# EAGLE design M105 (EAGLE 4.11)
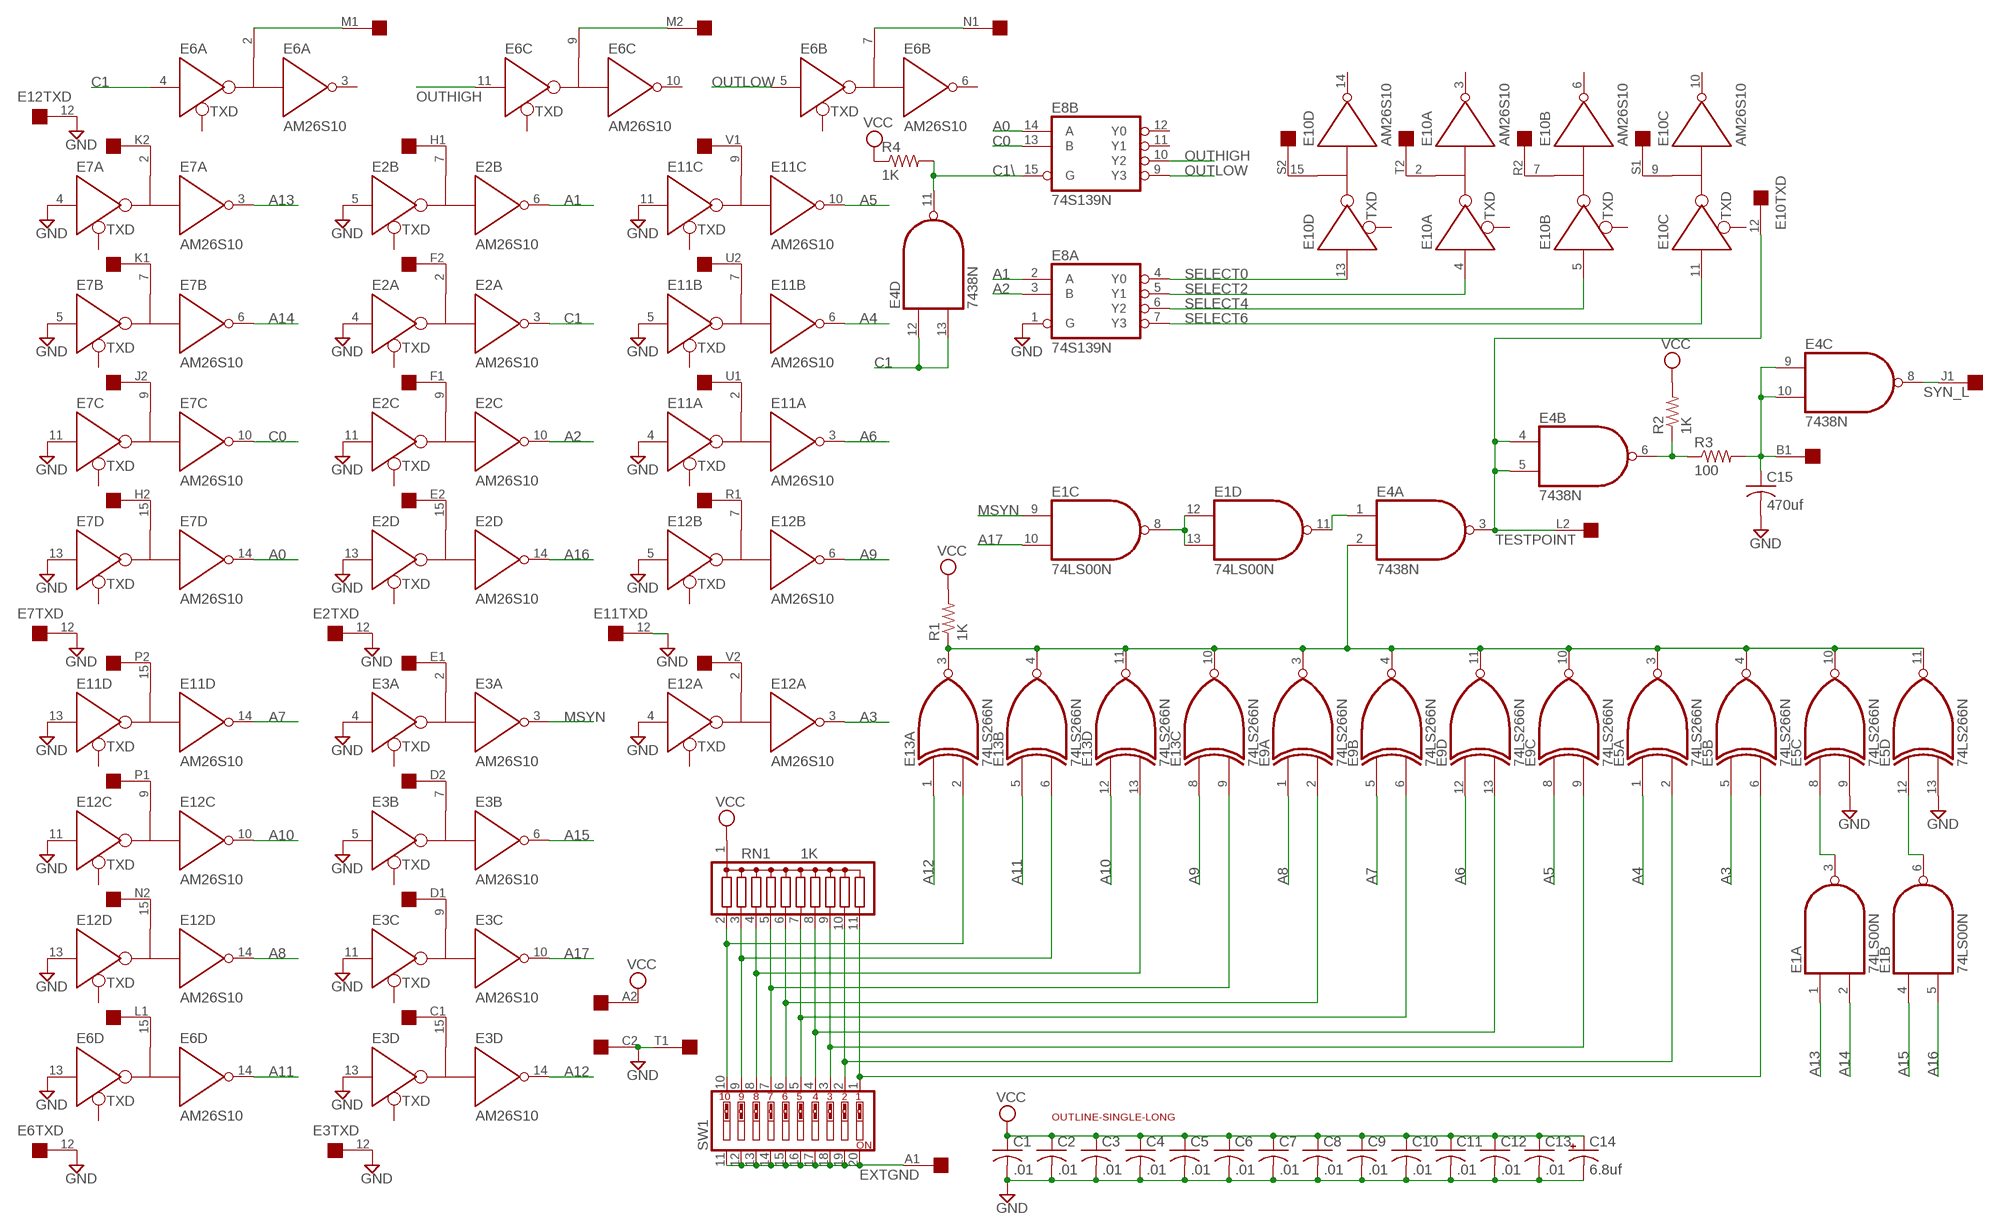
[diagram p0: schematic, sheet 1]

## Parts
C1  .01  C-US050-025X075  [C050-025X075]
C2  .01  C-US050-025X075  [C050-025X075]
C3  .01  C-US050-025X075  [C050-025X075]
C4  .01  C-US050-025X075  [C050-025X075]
C5  .01  C-US050-025X075  [C050-025X075]
C6  .01  C-US050-025X075  [C050-025X075]
C7  .01  C-US050-025X075  [C050-025X075]
C8  .01  C-US050-025X075  [C050-025X075]
C9  .01  C-US050-025X075  [C050-025X075]
C10  .01  C-US050-025X075  [C050-025X075]
C11  .01  C-US050-025X075  [C050-025X075]
C12  .01  C-US050-025X075  [C050-025X075]
C13  .01  C-US050-025X075  [C050-025X075]
C14  6.8uf  CPOL-USE15-5AXIAL  [E15-5]
C15  470uf  C-US050-025X075  [C050-025X075]
E1  74LS00N  [DIL14]
E2  AM26S10  [DIL16]
E3  AM26S10  [DIL16]
E4  7438N  [DIL14]
E5  74LS266N  [DIL14]
E6  AM26S10  [DIL16]
E7  AM26S10  [DIL16]
E8  74S139N  [DIL16]
E9  74LS266N  [DIL14]
E10  AM26S10  [DIL16]
E11  AM26S10  [DIL16]
E12  AM26S10  [DIL16]
E13  74LS266N  [DIL14]
R1  1K  R-US_0207/10  [0207/10]
R2  1K  R-US_0207/10  [0207/10]
R3  100  R-US_0207/10  [0207/10]
R4  1K  R-US_0207/10  [0207/10]
RN1  1K  G10R  [SIL11]
SW1  SW_DIP-10  [EDG-10]
U$1  SINGLE  [EDGE-CON2]
U$2  OUTLINE-SINGLE-LONG  [SINGLE-LONG]

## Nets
A0: E7.14(D:R) E8.14(B:A)
A1: E2.6(B:R) E8.2(A:A)
A2: E2.10(C:R) E8.3(A:B)
A3: E5.5(B:I0) E12.3(A:R)
A4: E5.1(A:I0) E11.6(B:R)
A5: E9.8(C:I0) E11.10(C:R)
A6: E9.12(D:I0) E11.3(A:R)
A7: E9.5(B:I0) E11.14(D:R)
A8: E9.1(A:I0) E12.14(D:R)
A9: E12.6(B:R) E13.8(C:I0)
A10: E12.10(C:R) E13.12(D:I0)
A11: E6.14(D:R) E13.5(B:I0)
A12: E3.14(D:R) E13.1(A:I0)
A13: E1.1(A:I0) E7.3(A:R)
A14: E1.2(A:I1) E7.6(B:R)
A15: E1.4(B:I0) E3.6(B:R)
A16: E1.5(B:I1) E2.14(D:R)
A17: E1.10(C:I1) E3.10(C:R)
C0: E7.10(C:R) E8.13(B:B)
C1: E2.3(A:R) E4.12(D:I0) E4.13(D:I1) E6.4(A:D)
C1\: E4.11(D:O) E8.15(B:G) R4.2
EXTGND: SW1.11 SW1.12 SW1.13 SW1.14 SW1.15 SW1.16 SW1.17 SW1.18 SW1.19 SW1.20 U$1.A1
GND: C1.2 C2.2 C3.2 C4.2 C5.2 C6.2 C7.2 C8.2 C9.2 C10.2 C11.2 C12.2 C13.2 C14.- C15.2 E2.4(A:D) E2.5(B:D) E2.11(C:D) E2.12(TXD:TXD) E2.13(D:D) E3.4(A:D) E3.5(B:D) E3.11(C:D) E3.12(TXD:TXD) E3.13(D:D) E5.9(C:I1) E5.13(D:I1) E6.12(TXD:TXD) E6.13(D:D) E7.4(A:D) E7.5(B:D) E7.11(C:D) E7.12(TXD:TXD) E7.13(D:D) E8.1(A:G) E11.4(A:D) E11.5(B:D) E11.11(C:D) E11.12(TXD:TXD) E11.13(D:D) E12.4(A:D) E12.5(B:D) E12.11(C:D) E12.12(TXD:TXD) E12.13(D:D) U$1.C2 U$1.T1
MSYN: E1.9(C:I0) E3.3(A:R)
N$1: E3.2(A:B) U$1.E1
N$2: E3.7(B:B) U$1.D2
N$3: E3.9(C:B) U$1.D1
N$4: E3.15(D:B) U$1.C1
N$5: E2.7(B:B) U$1.H1
N$6: E2.2(A:B) U$1.F2
N$7: E2.9(C:B) U$1.F1
N$8: E2.15(D:B) U$1.E2
N$9: E7.2(A:B) U$1.K2
N$10: E7.7(B:B) U$1.K1
N$11: E7.9(C:B) U$1.J2
N$12: E7.15(D:B) U$1.H2
N$13: E11.15(D:B) U$1.P2
N$14: E12.9(C:B) U$1.P1
N$15: E12.15(D:B) U$1.N2
N$16: E6.15(D:B) U$1.L1
N$17: E12.7(B:B) U$1.R1
N$18: E12.2(A:B) U$1.V2
N$19: E11.2(A:B) U$1.U1
N$20: E11.7(B:B) U$1.U2
N$21: E11.9(C:B) U$1.V1
N$22: E4.6(B:O) R2.1 R3.1
N$23: E10.15(D:B) U$1.S2
N$24: E10.2(A:B) U$1.T2
N$25: E10.7(B:B) U$1.R2
N$26: E10.9(C:B) U$1.S1
N$27: E6.2(A:B) U$1.M1
N$28: E6.9(C:B) U$1.M2
N$29: E1.3(A:O) E5.8(C:I0)
N$30: E1.6(B:O) E5.12(D:I0)
N$31: E1.8(C:O) E1.12(D:I0) E1.13(D:I1)
N$33: E5.6(B:I1) RN1.11 SW1.1
N$34: E5.2(A:I1) RN1.10 SW1.2
N$35: E9.9(C:I1) RN1.9 SW1.3
N$36: E9.13(D:I1) RN1.8 SW1.4
N$37: E9.6(B:I1) RN1.7 SW1.5
N$38: E9.2(A:I1) RN1.6 SW1.6
N$39: E13.9(C:I1) RN1.5 SW1.7
N$40: E13.13(D:I1) RN1.4 SW1.8
N$41: E13.6(B:I1) RN1.3 SW1.9
N$42: E13.2(A:I1) RN1.2 SW1.10
N$43: E4.2(A:I1) E5.3(A:O) E5.4(B:O) E5.10(C:O) E5.11(D:O) E9.3(A:O) E9.4(B:O) E9.10(C:O) E9.11(D:O) E13.3(A:O) E13.4(B:O) E13.10(C:O) E13.11(D:O) R1.1
N$44: C15.1 E4.9(C:I0) E4.10(C:I1) R3.2 U$1.B1
N$45: E6.7(B:B) U$1.N1
N$46: E1.11(D:O) E4.1(A:I0)
OUTHIGH: E6.11(C:D) E8.10(B:Y2)
OUTLOW: E6.5(B:D) E8.9(B:Y3)
SELECT0: E8.4(A:Y0) E10.13(D:D)
SELECT2: E8.5(A:Y1) E10.4(A:D)
SELECT4: E8.6(A:Y2) E10.5(B:D)
SELECT6: E8.7(A:Y3) E10.11(C:D)
SYN_L: E4.8(C:O) U$1.J1
TESTPOINT: E4.3(A:O) E4.4(B:I0) E4.5(B:I1) E10.12(TXD:TXD) U$1.L2
VCC: C1.1 C2.1 C3.1 C4.1 C5.1 C6.1 C7.1 C8.1 C9.1 C10.1 C11.1 C12.1 C13.1 C14.+ R1.2 R2.2 R4.1 RN1.1 U$1.A2
Unconnected: E6.3(A:R) E6.6(B:R) E6.10(C:R) E8.11(B:Y1) E8.12(B:Y0) E10.3(A:R) E10.6(B:R) E10.10(C:R) E10.14(D:R) U$1.B2

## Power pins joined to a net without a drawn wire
GND: E1.7(P:GND) E2.1(GND:GND) E2.8(PWR:GND) E3.1(GND:GND) E3.8(PWR:GND) E4.7(P:GND) E5.7(P:GND) E6.1(GND:GND) E6.8(PWR:GND) E7.1(GND:GND) E7.8(PWR:GND) E8.8(P:GND) E9.7(P:GND) E10.1(GND:GND) E10.8(PWR:GND) E11.1(GND:GND) E11.8(PWR:GND) E12.1(GND:GND) E12.8(PWR:GND) E13.7(P:GND)
VCC: E1.14(P:VCC) E2.16(PWR:VCC) E3.16(PWR:VCC) E4.14(P:VCC) E5.14(P:VCC) E6.16(PWR:VCC) E7.16(PWR:VCC) E8.16(P:VCC) E9.14(P:VCC) E10.16(PWR:VCC) E11.16(PWR:VCC) E12.16(PWR:VCC) E13.14(P:VCC)

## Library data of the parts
C1-C13 C15 = rcl:C-US: CAPACITOR, American symbol
C14 = rcl:CPOL-US: POLARIZED CAPACITOR, American symbol
E1 = 74xx-jameco:74*00: Quad 2-input NAND gate
E2 E3 E6 E7 E10-E12 = dec-con:AM26S10: Bus Transceiver
E4 = 74xx-jameco:74*38: Quad 2-input NAND gate, open collector output
E5 E9 E13 = 74xx-jameco:74*266: Quadruple EXCLUSIVE-NOR (XNOR), open-collector
E8 = 74xx-jameco:74*139: Dual 2-line to 4-line DECODER/DEMULTIPLEXER
R1-R4 = rcl:R-US_: RESISTOR, American symbol
RN1 = resistor-sil:G10R: SIL RESISTOR
SW1 = special:SW_DIP-10: DIP SWITCH
U$1 = dec-con:SINGLE: Single-Height DEC board
U$2 = dec-con:OUTLINE-*: Board outlines for DEC boards.

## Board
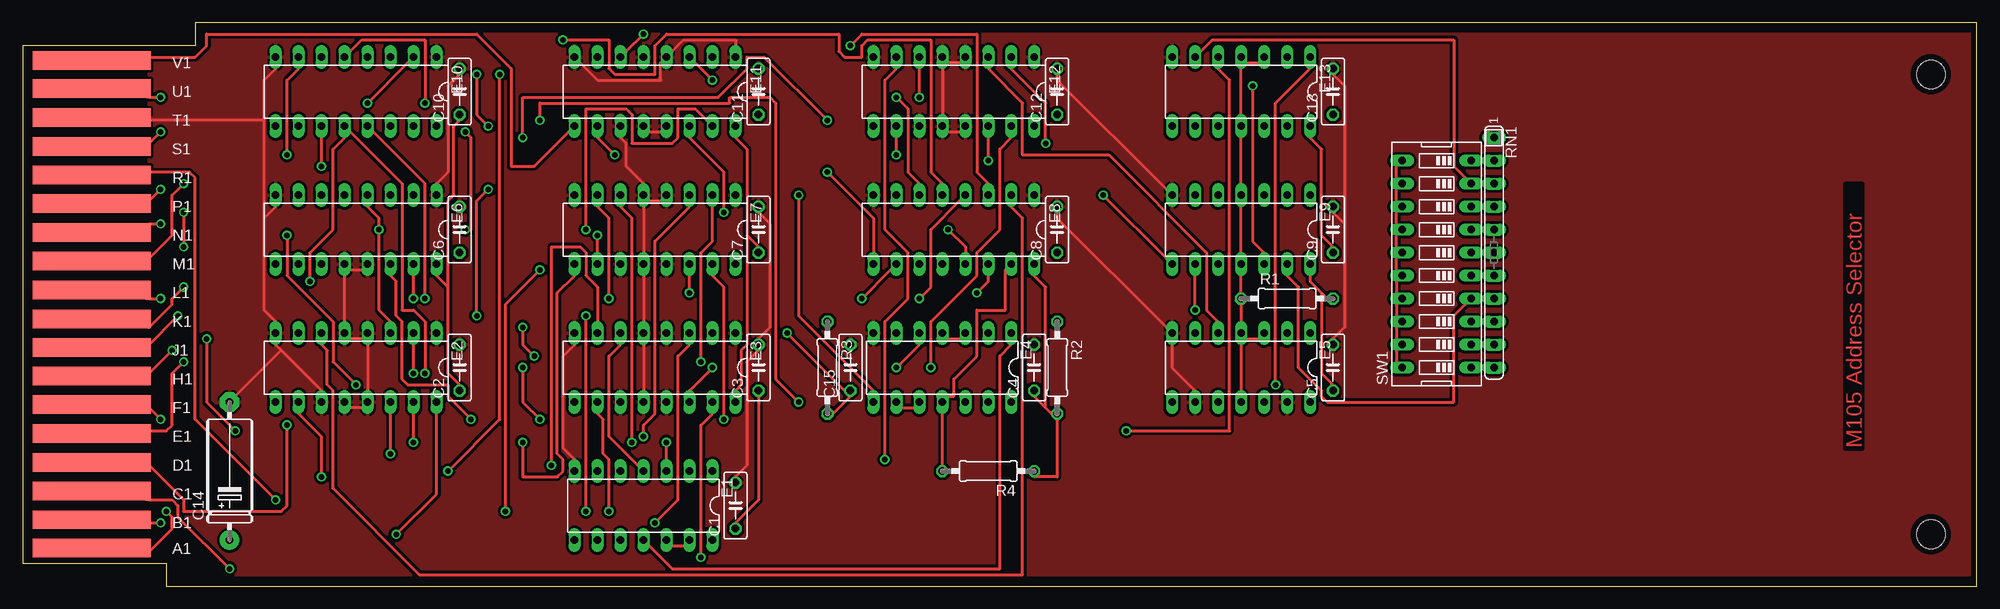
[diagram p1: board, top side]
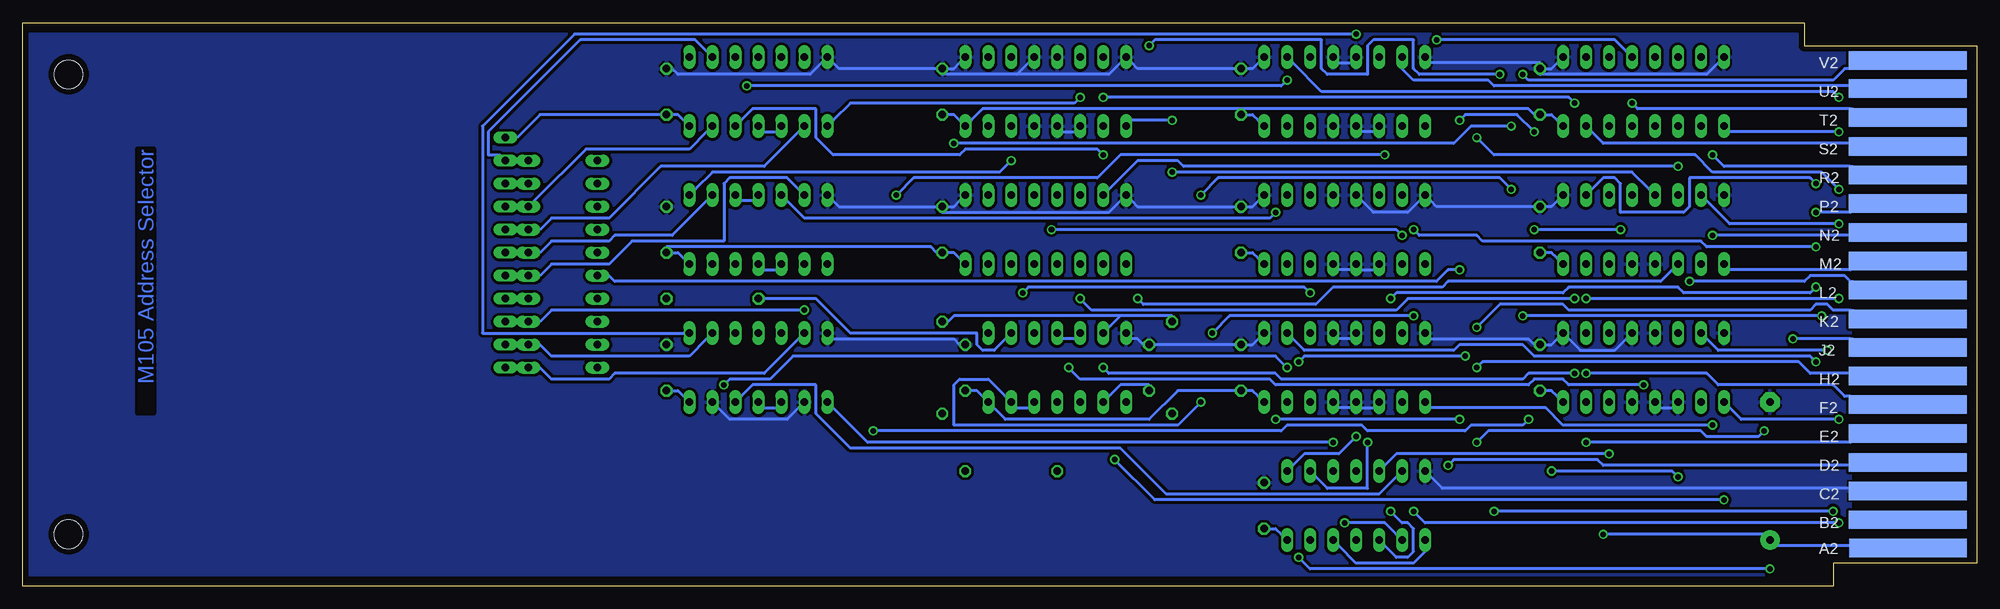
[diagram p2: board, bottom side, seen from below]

Size 215.9 x 62.23 mm. Coordinates in mm from the lower left corner, seen from the top.
Outline: 15.88,2.54 15.88,0
Copper layers (1*16): Top 0.035mm / dielectric 1.5mm / Bottom 0.035mm
Design rules "15mils": minimum track width 13mil, minimum drill 24mil, track to track 12mil, track to pad 10mil, pad to pad 10mil, via to via 10mil, smd to smd 10mil, copper to edge 25mil, drill to drill 10mil, minimum pad ring 10mil, minimum via ring 8mil, stop-mask expansion 0mil, vias tented up to drill 0mil, thermal gap 10mil

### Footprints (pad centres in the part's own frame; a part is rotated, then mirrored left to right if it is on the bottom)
C050-025X075 = drill 0.813 octagon: 1 -2.54,0; 2 2.54,0
E15-5 = drill 0.813 pad 2.159 round: + -7.62,0 | drill 0.813 pad 2.159 octagon: - 7.62,0
DIL14 = drill 0.813 long: 1 -7.62,-3.81; 2 -5.08,-3.81; 3 -2.54,-3.81; 4 0,-3.81; 5 2.54,-3.81; 6 5.08,-3.81; 7 7.62,-3.81; 8 7.62,3.81; 9 5.08,3.81; 10 2.54,3.81; 11 0,3.81; 12 -2.54,3.81; 13 -5.08,3.81; 14 -7.62,3.81
DIL16 = drill 0.813 long: 1 -8.89,-3.81; 2 -6.35,-3.81; 3 -3.81,-3.81; 4 -1.27,-3.81; 5 1.27,-3.81; 6 3.81,-3.81; 7 6.35,-3.81; 8 8.89,-3.81; 9 8.89,3.81; 10 6.35,3.81; 11 3.81,3.81; 12 1.27,3.81; 13 -1.27,3.81; 14 -3.81,3.81; 15 -6.35,3.81; 16 -8.89,3.81
0207/10 = drill 0.813 octagon: 1 -5.08,0; 2 5.08,0
SIL11 = drill 0.813 long: 1 -12.7,0; 2 -10.16,0; 3 -7.62,0; 4 -5.08,0; 5 -2.54,0; 6 0,0; 7 2.54,0; 8 5.08,0; 9 7.62,0; 10 10.16,0; 11 12.7,0
EDG-10 = drill 0.813 long: 1 -11.43,-3.81; 2 -8.89,-3.81; 3 -6.35,-3.81; 4 -3.81,-3.81; 5 -1.27,-3.81; 6 1.27,-3.81; 7 3.81,-3.81; 8 6.35,-3.81; 9 8.89,-3.81; 10 11.43,-3.81; 11 11.43,3.81; 12 8.89,3.81; 13 6.35,3.81; 14 3.81,3.81; 15 1.27,3.81; 16 -1.27,3.81; 17 -3.81,3.81; 18 -6.35,3.81; 19 -8.89,3.81; 20 -11.43,3.81
EDGE-CON2 = smd 13.017 x 2.032: A1 7.633,4.207; B1 7.639,7.327; C1 7.636,10.489; D1 7.633,13.665; E1 7.642,16.84; F1 7.642,20.041; H1 7.642,23.19; J1 7.642,26.34; K1 7.642,29.515; L1 7.642,32.69; M1 7.642,35.89; N1 7.642,39.04; P1 7.642,42.24; R1 7.642,45.39; S1 7.642,48.565; T1 7.642,51.74; U1 7.642,54.966; V1 7.642,58.026 | smd 13.017 x 2.032 bottom: A2 7.614,4.207; B2 7.642,7.328; C2 7.617,10.49; D2 7.642,13.665; E2 7.642,16.84; F2 7.617,20.041; H2 7.617,23.19; J2 7.642,26.34; K2 7.642,29.515; L2 7.642,32.69; M2 7.642,35.89; N2 7.642,39.04; P2 7.642,42.24; R2 7.642,45.39; S2 7.642,48.565; T2 7.642,51.74; U2 7.642,54.966; V2 7.642,58.026
SINGLE-LONG = hole 3.175: 210.82,56.515; 210.82,5.715

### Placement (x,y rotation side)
C1  78.74,8.89 90 top
C2  48.26,24.13 90 top
C3  81.28,24.13 90 top
C4  111.76,24.13 90 top
C5  144.78,24.13 90 top
C6  48.26,39.37 90 top
C7  81.28,39.37 90 top
C8  114.3,39.37 90 top
C9  144.78,39.37 90 top
C10  48.26,54.61 90 top
C11  81.28,54.61 90 top
C12  114.3,54.61 90 top
C13  144.78,54.61 90 top
C14  22.86,12.7 90 top
C15  91.44,24.13 90 top
E1  68.58,8.89 180 top
E2  36.83,24.13 180 top
E3  69.85,24.13 180 top
E4  101.6,24.13 180 top
E5  134.62,24.13 180 top
E6  36.83,39.37 180 top
E7  69.85,39.37 180 top
E8  102.87,39.37 180 top
E9  134.62,39.37 180 top
E10  36.83,54.61 180 top
E11  69.85,54.61 180 top
E12  102.87,54.61 180 top
E13  134.62,54.61 180 top
R1  139.7,31.75 0 top
R2  114.3,24.13 270 top
R3  88.9,24.13 270 top
R4  106.68,12.7 180 top
RN1  162.56,36.83 270 top
SW1  156.21,35.56 90 top
U$1  0,0 0 top
U$2  0,0 0 top

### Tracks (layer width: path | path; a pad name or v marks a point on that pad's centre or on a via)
A0  (via drill 0.61)
  Top 0.33: v73.66,32.38 73.66,34.29 E7.14 | v105.41,32.38 106.68,33.66 106.68,34.29 E8.14
  Bottom 0.33: v73.66,32.38 74.3,33.02 104.78,33.02 v105.41,32.38
A1
  Top 0.33: E2.6 33.02,26.67 33.66,26.04 33.66,22.23 34.29,21.59 34.29,10.79 43.82,1.27 110.49,1.27 110.49,40.64 109.22,41.91 E8.2
A2  (via drill 0.61)
  Top 0.33: v33.02,12.06 33.02,16.51 30.48,19.05 E2.10 | v46.99,12.7 52.71,18.41 v52.71,56.52 | v91.44,59.69 92.71,60.96 105.41,60.96 105.41,45.72 106.68,44.45 E8.3
  Bottom 0.33: v33.02,12.06 33.66,12.7 v46.99,12.7 | v52.71,56.52 61.6,56.52 62.23,57.15 62.23,60.33 66.68,60.33 67.31,59.69 67.31,56.52 71.76,56.52 72.39,57.15 72.39,60.33 90.81,60.33 v91.44,59.69
A3
  Top 0.33: E5.5 132.08,29.21 130.81,30.48 130.81,36.83 120.02,47.62 110.49,47.62 110.49,53.34 106.68,57.15 E12.3
A4  (via drill 0.61)
  Top 0.33: v68.58,60.96 66.68,59.05 E11.6
  Bottom 0.33: v68.58,60.96 154.94,60.96 165.1,50.8 165.1,27.94 142.88,27.94 E5.1
A5  (via drill 0.61)
  Top 0.33: v65.41,47.62 63.5,49.53 E11.10 | v119.38,43.18 126.37,36.2 E9.8
  Bottom 0.33: v65.41,47.62 94.62,47.62 97.16,45.09 117.48,45.09 v119.38,43.18
A6  (via drill 0.61)
  Top 0.33: v76.2,55.88 74.3,57.78 E11.3 | v135.89,55.24 135.89,38.1 137.16,36.83 E9.12
  Bottom 0.33: v76.2,55.88 76.84,55.24 v135.89,55.24
A7  (via drill 0.61)
  Top 0.33: v77.47,41.27 77.47,45.72 73.66,49.53 E11.14
  Bottom 0.33: v77.47,41.27 78.11,40.64 129.54,40.64 131.45,42.55 E9.5
A8  (via drill 0.61)
  Top 0.33: v106.68,46.99 106.68,49.53 E12.14
  Bottom 0.33: v106.68,46.99 107.95,45.72 139.7,45.72 141.61,43.81 E9.1
A9  (via drill 0.61)
  Top 0.33: v99.06,53.98 99.06,57.15 E12.6
  Bottom 0.33: v99.06,53.98 99.7,53.34 124.46,53.34 126.37,51.44 E13.8
A10  (via drill 0.61)
  Top 0.33: v96.52,47.62 96.52,49.53 E12.10
  Bottom 0.33: v96.52,47.62 97.16,48.26 111.76,48.26 112.4,47.62 126.37,47.62 128.27,49.53 128.27,52.7 135.26,52.7 136.53,51.44 E13.12
A11  (via drill 0.61)
  Top 0.33: v49.53,18.41 46.99,20.95 46.99,22.23 42.55,22.23 41.91,22.86 41.91,29.21 41.28,29.84 41.28,33.66 40.64,34.29 E6.14 | v121.92,17.14 133.35,17.14 133.35,55.88 132.08,57.15 E13.5
  Bottom 0.33: v49.53,18.41 50.17,17.78 55.88,17.78 56.52,17.14 67.31,17.14 67.95,17.78 76.2,17.78 76.84,17.14 v121.92,17.14
A12  (via drill 0.61)
  Top 0.33: v76.2,24.13 73.66,21.59 E3.14 | v138.43,22.23 138.43,53.34 142.24,57.15 E13.1
  Bottom 0.33: v76.2,24.13 77.47,25.4 130.81,25.4 133.35,22.86 137.8,22.86 v138.43,22.23
A13  (via drill 0.61)
  Top 0.33: v68.58,16.51 68.58,17.78 69.85,19.05 69.85,38.1 73.66,41.91 E7.3
  Bottom 0.33: v68.58,16.51 70.49,14.61 74.3,14.61 75.57,13.34 E1.1
A14  (via drill 0.61)
  Top 0.33: v67.31,15.88 67.31,40.64 66.04,41.91 E7.6
  Bottom 0.33: v67.31,15.88 67.31,10.79 71.76,10.79 73.03,12.06 E1.2
A15
  Top 0.33: E1.4 67.95,13.34 64.77,16.51 64.77,25.4 66.04,26.67 E3.6
A16  (via drill 0.61)
  Top 0.33: v40.64,14.61 40.64,19.05 E2.14
  Bottom 0.33: v40.64,14.61 64.14,14.61 65.41,13.34 E1.5
A17  (via drill 0.61)
  Top 0.33: v64.77,8.26 64.77,13.97 64.14,14.61 64.14,18.41 63.5,19.05 E3.10
  Bottom 0.33: v64.77,8.26 63.5,6.99 62.87,6.99 62.23,6.35 62.23,3.81 62.87,3.17 64.14,3.17 65.41,4.45 E1.10
C0  (via drill 0.61)
  Top 0.33: v63.5,38.73 63.5,36.83 E7.10 | v102.24,39.37 104.14,37.47 104.14,36.83 E8.13
  Bottom 0.33: v63.5,38.73 64.14,39.37 v102.24,39.37
C1  (via drill 0.61)
  Top 0.33: E2.3 40.64,29.21 39.37,30.48 v39.37,39.37 39.37,40.64 38.1,41.91 E6.4 | v85.73,20.32 83.19,22.86 83.19,53.34 82.55,53.98 78.11,53.98 78.11,53.34 57.15,53.34 v57.15,51.44 | v48.9,50.16 49.53,49.53 49.53,39.37 v48.9,39.37
  Bottom 0.33: E4.12 104.78,19.68 106.05,19.68 E4.13 107.32,20.95 109.22,22.86 112.4,22.86 113.03,22.23 113.03,17.78 88.27,17.78 v85.73,20.32 | v57.15,51.44 56.52,52.07 50.8,52.07 v48.9,50.16 | v39.37,39.37 v48.9,39.37
C1\
  Top 0.33: R4.2 101.6,13.34 101.6,19.05 E4.11 102.24,20.95 102.87,20.95 102.87,22.86 105.41,25.4 105.41,30.48 108.59,30.48 108.59,34.92 E8.15
EXTGND  (via drill 0.61)
  Top 0.33: SW1.20 151.77,24.77 151.77,26.04 SW1.19 151.77,27.3 151.77,28.57 SW1.18 151.77,29.84 151.77,31.11 SW1.17 151.77,32.38 151.77,33.66 SW1.16 151.77,34.92 151.77,36.2 SW1.15 151.77,37.47 151.77,38.73 SW1.14 151.77,40.01 151.77,41.27 SW1.13 151.77,42.55 151.77,43.81 SW1.12 151.77,45.09 151.77,46.35 SW1.11 | v57.15,34.92 53.34,31.11 v53.34,8.26 | v15.88,8.26 16.51,7.62 16.51,6.35 13.97,3.81 U$1.A1
  Bottom 0.33: v57.15,34.92 58.42,34.92 59.69,33.66 150.5,33.66 151.13,34.29 SW1.16 | v15.88,8.26 v53.34,8.26
GND
  Top 0.33: E1.7 60.96,13.97 59.69,15.24 59.69,25.4 60.96,26.67 E3.8 | E6.13 37.47,34.92 36.2,34.92 E6.12 35.56,34.29 35.56,29.21 E2.5 36.2,27.3 37.47,27.3 E2.4 38.1,26.67 38.1,21.59 E2.13 37.47,19.68 36.2,19.68 E2.12 | 28.58,26.04 33.02,21.59 E2.11 | 28.58,26.04 27.94,26.67 E2.8 27.94,29.21 26.67,30.48 26.67,40.64 | 26.67,40.64 27.94,41.91 E6.8 | 26.67,40.64 26.67,51.44 | 26.67,51.44 26.67,55.88 27.94,57.15 E10.8 | 28.58,26.04 23.5,20.95 C14.- | 26.67,51.44 13.97,51.44 U$1.T1 | E5.9 129.54,21.59 127,24.13 127,26.67 E5.7 126.37,28.57 114.3,40.64 114.3,41.27 C8.2 | C1.2 78.74,12.06 80.01,13.34 80.01,24.77 81.28,26.04 C3.2 81.28,27.3 82.55,28.57 82.55,40.01 81.28,41.27 C7.2 | E3.12 68.58,21.59 68.58,26.67 E3.5 68.58,29.21 68.58,34.29 E7.12 68.58,36.83 68.58,41.91 E7.5 | E11.13 70.49,50.16 69.22,50.16 E11.12 | E7.5 69.22,42.55 70.49,42.55 E7.4 | E11.11 66.04,49.53 66.68,48.9 66.68,46.35 68.58,44.45 E7.5 | E11.1 78.74,59.69 78.74,60.33 73.03,60.33 71.76,59.05 E11.4 70.49,57.78 70.49,55.88 63.5,55.88 61.6,57.78 E11.8 | 146.05,40.01 146.05,28.57 144.78,27.3 C5.2 | 146.05,40.01 144.78,41.27 C9.2 | 146.05,40.01 146.05,55.24 144.78,56.52 C13.2 | E12.4 103.51,57.78 102.24,57.78 E12.5 101.6,57.15 101.6,52.07 E12.12 102.24,50.16 103.51,50.16 E12.13 | E6.1 45.72,44.45 46.99,45.72 46.99,55.24 48.26,56.52 C10.2 | E9.7 126.37,43.81 114.3,55.88 114.3,56.52 C12.2
  Bottom 0.33: E3.8 60.33,27.3 49.53,27.3 48.9,26.67 C2.2 47.63,26.67 46.99,26.67 46.36,27.3 E2.1 45.09,27.3 43.82,26.04 40.01,26.04 38.74,27.3 E2.4 | E2.11 33.66,19.68 34.93,19.68 E2.12 | U$1.C2 13.97,10.79 59.06,10.79 60.33,12.06 E1.7 | C4.2 112.4,26.67 113.03,27.3 126.37,27.3 E5.7 | E5.13 139.07,19.68 137.8,18.41 131.45,18.41 130.18,19.68 E5.9 | E4.7 93.35,27.3 92.71,27.3 92.08,26.67 C15.2 90.81,26.67 81.92,26.67 C3.2 80.65,26.67 80.01,26.67 79.38,27.3 E3.1 | E7.1 79.38,42.55 80.01,41.91 80.65,41.91 C7.2 81.92,41.91 92.71,41.91 93.35,42.55 E8.8 94.62,42.55 95.89,41.27 114.3,41.27 C8.2 | E8.1 112.4,42.55 113.03,41.91 113.67,41.91 C8.2 | E9.7 126.37,42.55 125.73,41.91 114.94,41.91 C8.2 | E6.1 46.36,42.55 46.99,41.91 47.63,41.91 C6.2 48.9,41.91 59.69,41.91 60.33,42.55 E7.8 61.6,42.55 62.87,41.27 66.68,41.27 67.95,42.55 E7.5 | E3.5 69.22,27.3 70.49,27.3 E3.4 | E3.11 66.68,19.68 67.95,19.68 E3.12 69.22,19.68 70.49,19.68 E3.13 | E11.11 66.68,50.16 67.95,50.16 E11.12 | E7.11 66.68,34.92 67.95,34.92 E7.12 69.22,34.92 70.49,34.92 E7.13 | E10.1 46.36,57.78 46.99,57.15 47.63,57.15 C10.2 | E11.8 60.33,57.78 48.26,57.78 C10.2 | E11.5 69.22,57.78 70.49,57.78 E11.4 | E11.1 79.38,57.78 80.01,57.15 80.65,57.15 C11.2 81.92,57.15 92.71,57.15 93.35,57.78 E12.8 94.62,57.78 95.89,56.52 106.05,56.52 | E12.11 99.7,50.16 100.97,50.16 E12.12 | E12.1 112.4,57.78 113.03,57.15 113.67,57.15 C12.2 | C12.2 114.94,57.15 125.73,57.15 126.37,57.78 E13.7 127.64,57.78 128.91,56.52 143.51,56.52 144.15,57.15 C13.2 | 106.05,56.52 104.78,57.78 E12.4 | 106.05,56.52 114.3,56.52 C12.2 | E10.8 28.58,57.78 29.85,56.52 48.26,56.52 C10.2
  pour Bottom (isolate 0.305): 13.97,60.96 215.9,60.96 215.9,1.27 13.97,1.27
  pour Top (isolate 0.305): 13.97,60.96 215.9,60.96 215.9,1.27 13.97,1.27
MSYN  (via drill 0.61)
  Top 0.33: v69.85,6.99 72.39,9.53 72.39,25.4 73.66,26.67 E3.3
  Bottom 0.33: v69.85,6.99 65.41,6.99 64.14,5.71 E1.9
N$1  (via drill 0.61)
  Top 0.33: v17.78,24.77 16.51,23.5 16.51,17.78 15.88,17.14 13.97,17.14 U$1.E1
  Bottom 0.33: v17.78,24.77 18.42,25.4 48.9,25.4 50.17,26.67 57.15,26.67 57.79,26.04 74.3,26.04 75.57,27.3 E3.2
N$2  (via drill 0.61)
  Top 0.33: v58.42,13.34 58.42,37.47 61.6,37.47 62.23,36.83 62.23,34.29 63.5,33.02 63.5,29.21 E3.7
  Bottom 0.33: v58.42,13.34 57.79,13.97 41.91,13.97 41.28,13.34 13.97,13.34 U$1.D2
N$3  (via drill 0.61)
  Top 0.33: v29.21,17.78 29.21,8.89 28.58,8.26 17.78,8.26 17.78,9.53 13.97,13.34 U$1.D1
  Bottom 0.33: v29.21,17.78 45.72,17.78 47.63,19.68 60.33,19.68 E3.9
N$4  (via drill 0.61)
  Top 0.33: v74.93,3.17 74.93,17.78 76.2,19.05 E3.15 | v22.86,1.91 17.15,7.62 17.15,8.89 16.51,9.53 13.97,9.53 U$1.C1
  Bottom 0.33: v74.93,3.17 73.66,1.91 v22.86,1.91
N$5  (via drill 0.61)
  Top 0.33: v16.51,26.04 13.97,23.5 U$1.H1
  Bottom 0.33: v16.51,26.04 28.58,26.04 29.85,27.3 E2.7
N$6  (via drill 0.61)
  Top 0.33: v43.18,23.5 43.18,26.67 E2.2
  Bottom 0.33: v43.18,23.5 29.85,23.5 28.58,22.23 15.88,22.23 14.61,20.95 13.97,20.95 U$1.F2
N$7  (via drill 0.61)
  Top 0.33: v15.24,18.41 13.97,19.68 U$1.F1
  Bottom 0.33: v15.24,18.41 26.04,18.41 27.31,19.68 E2.9
N$8  (via drill 0.61)
  Top 0.33: v43.18,15.88 43.18,19.05 E2.15
  Bottom 0.33: v43.18,15.88 13.97,15.88 U$1.E2
N$9  (via drill 0.61)
  Top 0.33: v74.93,24.77 74.93,36.83 76.2,38.1 76.2,41.91 E7.2 | v56.52,25.4 55.25,26.67 v55.25,28.57
  Bottom 0.33: v74.93,24.77 74.3,25.4 v56.52,25.4 | v55.25,28.57 52.71,31.11 45.72,31.11 45.09,30.48 18.42,30.48 17.78,31.11 16.51,31.11 15.88,30.48 13.97,30.48 U$1.K2
N$10  (via drill 0.61)
  Top 0.33: v64.77,31.75 64.77,40.64 63.5,41.91 E7.7 | v17.78,33.02 16.51,31.75 16.51,31.11 13.97,28.57 U$1.K1
  Bottom 0.33: v64.77,31.75 64.14,32.38 45.72,32.38 45.09,33.02 33.02,33.02 32.39,32.38 18.42,32.38 v17.78,33.02
N$11  (via drill 0.61)
  Top 0.33: v55.25,15.88 55.25,12.06 59.06,12.06 59.69,12.7 59.69,13.97 59.06,14.61 59.06,32.38 60.96,34.29 E7.9 | v23.5,17.14 20.32,20.32 v20.32,27.3
  Bottom 0.33: v55.25,15.88 53.98,17.14 30.48,17.14 29.85,16.51 24.13,16.51 v23.5,17.14 | v20.32,27.3 13.97,27.3 U$1.J2
N$12  (via drill 0.61)
  Top 0.33: v77.47,18.41 77.47,33.02 76.2,34.29 E7.15 | v57.15,18.41 55.25,20.32 v55.25,24.13
  Bottom 0.33: v57.15,18.41 v77.47,18.41 | v55.25,24.13 54.61,24.77 19.69,24.77 18.42,23.5 13.97,23.5 U$1.H2
N$13  (via drill 0.61)
  Top 0.33: v62.23,39.37 62.23,52.7 66.68,52.7 67.31,52.07 67.31,48.9 71.76,48.9 72.39,49.53 72.39,52.7 74.3,52.7 75.57,51.44 E11.15 | v17.78,41.27 v17.78,37.47
  Bottom 0.33: v62.23,39.37 61.6,38.73 55.25,38.73 54.61,38.1 30.48,38.1 29.85,37.47 v17.78,37.47 | v17.78,41.27 13.97,41.27 U$1.P2
N$14  (via drill 0.61)
  Top 0.33: v88.9,51.44 81.92,58.42 80.01,58.42 80.01,57.15 76.84,53.98 55.25,53.98 v55.25,49.53 | v15.24,43.81 13.97,42.55 U$1.P1
  Bottom 0.33: v88.9,51.44 93.35,51.44 E12.9 | v55.25,49.53 53.34,47.62 31.12,47.62 29.21,45.72 17.15,45.72 v15.24,43.81
N$15  (via drill 0.61)
  Top 0.33: v100.33,24.13 100.33,29.21 105.41,34.29 105.41,36.83 107.95,39.37 107.95,48.26 109.22,49.53 E12.15 | v36.83,22.23 34.29,24.77 34.29,29.21 29.21,34.29 v29.21,38.73
  Bottom 0.33: v100.33,24.13 99.06,22.86 78.11,22.86 77.47,22.23 49.53,22.23 48.9,22.86 45.72,22.86 45.09,22.23 v36.83,22.23 | v29.21,38.73 13.97,38.73 U$1.N2
N$16  (via drill 0.61)
  Top 0.33: v43.18,31.75 43.18,34.29 E6.15 | v15.24,31.75 13.97,31.75 U$1.L1
  Bottom 0.33: v15.24,31.75 v43.18,31.75
N$17  (via drill 0.61)
  Top 0.33: v95.25,13.97 95.25,29.21 97.79,31.75 97.79,36.83 95.25,39.37 95.25,55.88 96.52,57.15 E12.7 | v27.94,9.53 19.05,18.41 19.05,45.09 18.42,45.72 13.97,45.72 U$1.R1
  Bottom 0.33: v95.25,13.97 90.81,9.53 v27.94,9.53
N$18  (via drill 0.61)
  Top 0.33: v113.03,48.9 113.03,53.34 109.22,57.15 E12.2 | v51.44,50.8 50.17,52.07 v50.17,56.52
  Bottom 0.33: v113.03,48.9 57.79,48.9 55.88,50.8 v51.44,50.8 | v50.17,56.52 49.53,55.88 15.88,55.88 14.61,57.15 13.97,57.15 U$1.V2
N$19  (via drill 0.61)
  Top 0.33: v15.24,53.98 13.97,53.98 U$1.U1
  Bottom 0.33: v15.24,53.98 15.88,54.61 72.39,54.61 75.57,57.78 E11.2
N$20
  Bottom 0.33: E11.7 63.5,57.15 62.23,55.88 53.98,55.88 53.34,55.24 13.97,55.24 U$1.U2
N$21
  Top 0.33: E11.9 60.33,50.16 56.52,46.35 53.98,46.35 53.98,57.15 50.17,60.96 20.32,60.96 20.32,59.69 19.05,58.42 13.97,58.42 U$1.V1
N$22
  Bottom 0.33: 94.62,29.84 95.89,28.57 E4.6 | 94.62,29.84 88.9,29.84 R3.1 | 94.62,29.84 113.03,29.84 113.67,29.21 R2.1
N$23
  Bottom 0.33: E10.15 42.55,50.16 41.28,48.9 13.97,48.9 U$1.S2
N$24  (via drill 0.61)
  Top 0.33: v38.1,53.34 42.55,57.78 E10.2
  Bottom 0.33: v38.1,53.34 37.47,52.7 13.97,52.7 U$1.T2
N$25  (via drill 0.61)
  Top 0.33: v29.21,47.62 29.21,55.88 30.48,57.15 E10.7
  Bottom 0.33: v29.21,47.62 27.94,46.35 13.97,46.35 U$1.R2
N$26  (via drill 0.61)
  Top 0.33: v15.24,50.16 13.97,48.9 U$1.S1
  Bottom 0.33: v15.24,50.16 27.31,50.16 E10.9
N$27  (via drill 0.61)
  Top 0.33: v17.78,44.45 16.51,43.18 16.51,38.73 13.97,36.2 U$1.M1
  Bottom 0.33: v17.78,44.45 18.42,45.09 31.75,45.09 31.75,41.91 32.39,41.27 39.37,41.27 39.37,44.45 40.01,45.09 41.28,45.09 42.55,43.81 E6.2
N$28
  Bottom 0.33: E6.9 27.31,34.92 13.97,34.92 U$1.M2
N$29  (via drill 0.61)
  Top 0.33: v71.12,15.88 71.12,13.97 E1.3
  Bottom 0.33: v71.12,15.88 122.56,15.88 126.37,19.68 E5.8
N$30
  Bottom 0.33: E1.6 64.14,12.06 66.04,10.16 89.54,10.16 94.62,15.24 124.46,15.24 128.27,19.05 128.27,22.23 135.26,22.23 136.53,20.95 E5.12
N$31
  Top 0.33: E1.13 73.03,4.45 71.76,4.45 E1.12
  Bottom 0.33: E1.8 60.96,3.81 62.23,2.54 68.58,2.54 70.49,4.45 E1.12
N$33
  Top 0.33: SW1.1 161.29,24.13 RN1.11
  Bottom 0.33: E5.6 130.18,27.3 133.99,23.5 150.5,23.5 151.13,22.86 157.48,22.86 158.75,24.13 SW1.1
N$34
  Top 0.33: SW1.2 161.29,26.67 RN1.10
  Bottom 0.33: E5.2 140.34,27.3 142.24,25.4 157.48,25.4 158.75,26.67 SW1.2
N$35  (via drill 0.61)
  Top 0.33: SW1.3 161.29,29.21 RN1.9 | v129.54,30.48 129.54,34.29 E9.9
  Bottom 0.33: v129.54,30.48 157.48,30.48 158.75,29.21 SW1.3
N$36
  Top 0.33: RN1.8 161.29,31.75 SW1.4 159.39,31.11 158.12,29.84 158.12,20.32 144.15,20.32 143.51,20.95 143.51,21.59 140.97,24.13 140.97,33.02 139.7,34.29 E9.13
N$37
  Top 0.33: SW1.5 161.29,34.29 RN1.7
  Bottom 0.33: E9.6 130.18,43.81 131.45,45.09 137.8,45.09 138.43,44.45 138.43,38.1 148.59,38.1 151.13,35.56 157.48,35.56 158.75,34.29 SW1.5
N$38
  Top 0.33: SW1.6 161.29,36.83 RN1.6
  Bottom 0.33: E9.2 140.34,42.55 144.15,38.73 150.5,38.73 151.13,38.1 157.48,38.1 158.75,36.83 SW1.6
N$39
  Top 0.33: SW1.7 161.29,39.37 RN1.5
  Bottom 0.33: E13.9 130.18,50.16 133.99,46.35 145.42,46.35 151.13,40.64 157.48,40.64 158.75,39.37 SW1.7
N$40
  Top 0.33: SW1.8 161.29,41.91 RN1.4
  Bottom 0.33: E13.13 140.34,50.16 142.24,48.26 153.67,48.26 159.39,42.55 SW1.8
N$41
  Top 0.33: RN1.3 161.29,44.45 SW1.9 159.39,45.09 158.12,46.35 158.12,60.33 131.45,60.33 130.18,59.05 E13.6
N$42
  Top 0.33: SW1.10 161.29,46.99 RN1.2
  Bottom 0.33: E13.2 140.34,59.05 141.61,60.33 154.31,60.33 164.47,50.16 164.47,47.62 163.2,47.62 RN1.2
N$43
  Top 0.33: E5.4 135.26,27.3 136.53,27.3 E5.3 | E5.11 134.62,21.59 134.62,26.67 E5.4 | E13.3 136.53,57.78 135.26,57.78 E13.4 134.62,57.15 134.62,52.07 E13.11 134.62,49.53 134.62,44.45 E9.4 134.62,41.91 134.62,36.83 E9.11 134.62,34.29 134.62,32.38 R1.1 134.62,31.11 134.62,29.21 E5.4
  Bottom 0.33: E5.10 132.72,19.68 133.99,19.68 E5.11 | E13.10 132.72,50.16 133.99,50.16 E13.11 | E9.4 135.26,42.55 136.53,42.55 E9.3 | E9.10 132.72,34.92 133.99,34.92 E9.11 | E4.2 107.32,27.3 108.59,26.04 109.86,26.04 110.49,26.67 110.49,27.94 124.46,27.94 128.27,31.75 133.99,31.75 R1.1
N$44  (via drill 0.61)
  Top 0.33: E4.9 97.16,19.68 98.43,19.68 E4.10 | R3.2 89.54,19.05 91.44,20.95 C15.1 90.81,21.59 v84.46,27.94 | v62.23,8.26 v62.23,29.84 | v15.24,6.99 13.97,6.99 U$1.B1
  Bottom 0.33: E4.9 95.89,20.95 94.62,22.23 91.44,22.23 C15.1 | v84.46,27.94 82.55,29.84 v62.23,29.84 | v62.23,8.26 60.96,6.99 v15.24,6.99
N$45  (via drill 0.61)
  Top 0.33: v15.24,40.01 13.97,40.01 U$1.N1
  Bottom 0.33: v15.24,40.01 27.31,40.01 29.85,42.55 E6.7
N$46
  Top 0.33: E1.11 69.22,4.45 71.76,1.91 107.95,1.91 107.95,25.4 109.22,26.67 E4.1
OUTHIGH  (via drill 0.61)
  Top 0.33: v92.71,31.75 95.89,34.92 E8.10
  Bottom 0.33: v92.71,31.75 92.08,31.11 73.03,31.11 71.12,33.02 59.06,33.02 58.42,33.66 34.93,33.66 33.66,34.92 E6.11
OUTLOW  (via drill 0.61)
  Top 0.33: v88.9,45.72 93.98,40.64 93.98,36.83 E8.9
  Bottom 0.33: v88.9,45.72 38.1,45.72 36.2,43.81 E6.5
SELECT0  (via drill 0.61)
  Top 0.33: v44.45,31.75 44.45,44.45 38.74,50.16 E10.13 | v99.06,31.75 100.33,33.02 100.33,39.37 103.51,42.55 E8.4
  Bottom 0.33: v44.45,31.75 62.87,31.75 64.14,30.48 97.79,30.48 v99.06,31.75
SELECT2  (via drill 0.61)
  Top 0.33: v59.69,60.33 64.77,60.33 64.77,57.15 65.41,56.52 69.85,56.52 69.85,59.69 71.12,60.96 90.17,60.96 90.17,59.05 90.81,58.42 92.71,58.42 92.71,59.69 93.35,60.33 100.33,60.33 100.33,45.72 101.6,44.45 E8.5
  Bottom 0.33: v59.69,60.33 40.01,60.33 38.74,59.05 E10.4
SELECT4  (via drill 0.61)
  Top 0.33: v44.45,53.34 44.45,60.33 37.47,60.33 36.2,59.05 E10.5 | v96.52,53.98 97.79,52.7 97.79,45.72 99.06,44.45 E8.6
  Bottom 0.33: v44.45,53.34 45.09,53.98 v96.52,53.98
SELECT6  (via drill 0.61)
  Top 0.33: v33.02,46.35 33.02,49.53 E10.11
  Bottom 0.33: v33.02,46.35 87.63,46.35 88.27,46.99 92.71,46.99 95.89,43.81 E8.7
SYN_L  (via drill 0.61)
  Top 0.33: v85.73,43.18 85.73,29.84 93.98,21.59 E4.8 | v51.44,43.81 50.17,42.55 v50.17,29.84 | v17.15,29.84 13.97,26.67 U$1.J1
  Bottom 0.33: v85.73,43.18 83.82,45.09 52.71,45.09 v51.44,43.81 | v17.15,29.84 v50.17,29.84
TESTPOINT  (via drill 0.61)
  Top 0.33: E4.3 103.51,27.3 102.24,27.3 E4.4 | v31.75,33.66 31.75,36.83 34.29,39.37 34.29,48.26 35.56,49.53 E10.12 36.2,50.16 41.91,44.45 41.91,30.48 43.18,30.48 44.45,29.21 v44.45,23.5 | v96.52,24.13 99.06,26.67 E4.5
  Bottom 0.33: E4.5 99.7,27.3 100.97,27.3 E4.4 | v31.75,33.66 19.05,33.66 18.42,34.29 14.61,34.29 13.97,33.66 U$1.L2 | v96.52,24.13 95.89,23.5 77.47,23.5 76.84,22.86 50.17,22.86 49.53,23.5 v44.45,23.5
VCC  (via drill 0.61)
  Top 0.33: 113.03,19.68 111.76,20.95 C4.1 | 113.03,19.68 113.67,19.05 R2.2 114.3,18.41 114.3,12.06 111.76,12.06 R4.1 | 113.03,19.68 113.03,33.02 111.76,34.29 E8.16 | 143.51,32.38 142.24,33.66 142.24,34.29 E9.14 | 143.51,32.38 144.15,31.75 R1.2 | 143.51,32.38 143.51,23.5 144.78,22.23 C5.1 | C9.1 144.78,37.47 143.51,38.73 143.51,48.26 142.24,49.53 E13.14 | 46.99,33.02 46.99,23.5 48.26,22.23 C2.1 | 46.99,33.02 45.72,34.29 E6.16 | 46.99,33.02 46.99,42.55 47.63,43.18 47.63,50.8 48.26,51.44 C10.1 | C1.1 78.74,6.99 81.28,9.53 81.28,20.95 C3.1 | 80.01,38.73 81.28,37.47 C7.1 | 80.01,38.73 80.01,48.26 78.74,49.53 E11.16 | 80.01,38.73 80.01,26.67 79.38,26.04 79.38,22.23 78.74,21.59 E3.16 | v41.28,5.71 45.72,10.16 45.72,19.05 E2.16
  Bottom 0.33: E8.16 112.4,36.2 113.03,36.83 113.67,36.83 C8.1 114.94,36.83 115.57,37.47 144.78,37.47 C9.1 144.15,36.83 143.51,36.83 142.88,36.2 E9.14 | C4.1 111.13,21.59 110.49,21.59 109.86,20.95 E4.14 108.59,19.68 107.32,18.41 91.44,18.41 88.27,21.59 81.92,21.59 C3.1 80.65,21.59 80.01,21.59 79.38,20.95 E3.16 | E5.14 142.88,20.95 143.51,21.59 144.15,21.59 C5.1 | E13.14 142.88,51.44 143.51,52.07 144.15,52.07 C13.1 145.42,52.07 158.75,52.07 161.29,49.53 RN1.1 | U$1.A2 13.97,4.45 22.23,4.45 C14.+ 23.5,5.71 v41.28,5.71 | E10.16 46.36,51.44 46.99,52.07 47.63,52.07 C10.1 48.9,52.07 49.53,52.7 81.28,52.7 | E2.16 46.36,20.95 46.99,21.59 47.63,21.59 C2.1 | E6.16 46.36,36.2 46.99,36.83 47.63,36.83 C6.1 | E1.14 76.84,5.71 77.47,6.35 78.11,6.35 C1.1 | C12.1 113.67,52.07 113.03,52.07 112.4,51.44 E12.16 111.13,51.44 109.86,52.7 81.28,52.7 | E7.16 79.38,36.2 80.01,36.83 80.65,36.83 C7.1 | E11.16 79.38,51.44 80.01,52.07 80.65,52.07 C11.1 | 81.28,52.7 C11.1 | 81.28,52.7 C11.1

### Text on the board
Top: M105 Address Selector
Bottom: M105 Address Selector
